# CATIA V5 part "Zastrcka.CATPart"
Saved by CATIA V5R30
Part number: Zastrcka
Definition: 2025_05_12_09_10_00_0871
Nomenclature: 2025_05_12_09_10_00_0871
Source: Unknown
Description: PART-2025_05_12_09_10_00_0871-DESC
Bounding box of the stored display mesh (mm): x -42.35 to 42.15, y -17.1 to 16.9, z -17.4 to 15
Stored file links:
  E:\Bakalarka\Model\Forma_v7\Zastrcka.CATPart
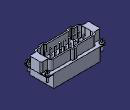
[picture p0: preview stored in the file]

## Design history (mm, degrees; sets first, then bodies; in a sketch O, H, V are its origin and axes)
Body1 "E2702_16B" (main body)
  Solid1: solid without history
